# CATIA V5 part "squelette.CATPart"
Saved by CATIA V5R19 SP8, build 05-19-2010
Part number: squelette
Bounding box of the stored display mesh (mm): x -290.933 to 290.933, y 0 to 1220, z -52.5 to 105
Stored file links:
  G:\EU_thinkMotion\CFAO_2010\MMS_groupe2\MMS_groupe2\A reprendre\splanchenault\Planchenault\squelette.CATPart
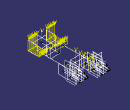
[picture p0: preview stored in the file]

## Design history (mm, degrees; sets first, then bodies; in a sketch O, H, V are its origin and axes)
Set1
  Plane1: type Offset, RefPlane zx-plane, Offset 200
  Plane2: type Offset, RefPlane zx-plane, Offset 300
  Plane3: type Offset, RefPlane yz-plane, Offset 200
  Plane4: type Offset, RefPlane yz-plane, Offset 200, reversed
  Plane5: type Offset, RefPlane zx-plane, Offset 750
  Plane6: type Offset, RefPlane zx-plane, Offset 850
  Plane7: type OffsetPt, RefPlane yz-plane, RefPoint Sketch6.P7
  Plane8: type OffsetPt, RefPlane Plane7, RefPoint Sketch6.P5
  Plane9: type OffsetPt, RefPlane Plane8, RefPoint Sketch7.P6
  Plane10: type OffsetPt, RefPlane Plane9, RefPoint Sketch7.P4
  Plane11: type OffsetPt, RefPlane Plane5, RefPoint Sketch8.P2
  Plane12: type OffsetPt, RefPlane Plane11, RefPoint Sketch13.P2
  Plane13: type OffsetPt, RefPlane Plane8, RefPoint Sketch14.P26
  Plane14: type OffsetPt, RefPlane Plane13, RefPoint Sketch14.P25
  Plane15: type OffsetPt, RefPlane Plane13, RefPoint Sketch14.P34
  Plane16: type OffsetPt, RefPlane Plane15, RefPoint Sketch14.P33
  Plane17: type OffsetPt, RefPlane Plane13, RefPoint Sketch14.P10
  Plane18: type OffsetPt, RefPlane Plane13, RefPoint Sketch14.P8
  Plane19: type OffsetPt, RefPlane Plane15, RefPoint Sketch15.P18
  Plane20: type OffsetPt, RefPlane Plane19, RefPoint Sketch15.P15
  Plane21: type OffsetPt, RefPlane Plane20, RefPoint Sketch15.P21
  Plane22: type OffsetPt, RefPlane Plane19, RefPoint Sketch15.P27
  Plane23: type OffsetPt, RefPlane Plane19, RefPoint Sketch15.P4
  Plane24: type OffsetPt, RefPlane Plane19, RefPoint Sketch15.P6
  Plane25: type OffsetPt, RefPlane Plane23, RefPoint Sketch15.P2
Body1 (main body)
  Sketch1 on yz-plane, origin (0, 0, 0), H (0, 1, 0), V (0, 0, 1)
    point P1 (0, 0)
    line L1 (0, 0) -> (380, 0)
    point P2 (380, 0)
    point P3 (380, 0)
    length L1 = 380
    coincidence: P1 O, P3 P2
    horizontal: L1 H
  Sketch2 on Plane1, origin (0, 200, 0), H (-1, 0, 0), V (0, 0, 1)
    point P1 (-200, 0)
    coincidence: P1 H
  Sketch3 on Plane2, origin (0, 300, 0), H (-1, 0, 0), V (0, 0, 1)
    point P1 (200, 0)
    coincidence: P1 H
  Sketch4 on Plane3, origin (200, 0, 0), H (0, 1, 0), V (0, 0, 1)
    line L1 (199.3543, 0) -> (749.3543, 0)
    point P1 (199.3543, 0)
    length L1 = 550
    coincidence: P1 H
    horizontal: L1 H
  Sketch5 on Plane4, origin (-200, 0, 0), H (0, 1, 0), V (0, 0, 1)
    line L1 (300, 0) -> (850, 0)
    point P1 (300, 0)
    length L1 = 550
    coincidence: P1 H
    horizontal: L1 H
  Sketch6 on Plane5, origin (0, 750, 0), H (-1, 0, 0), V (0, 0, 1)
    line L1 (-200, 0) -> (-200, 80)
    point P1 (-200, 0)
    point P2 (-200, 80)
    point P3 (-200, 80)
    point P4 (-200, 0)
    point P5 (-269.282, -40)
    line L2 (-200, 0) -> (-269.282, -40)
    point P7 (-130.718, -40)
    line L3 (-200, 0) -> (-130.718, -40)
    point P9 (-130.718, -40)
    point P10 (-269.282, -40)
    coincidence: P1 H, P3 P2, P4 P1, P9 P7, P10 P5
    vertical: L1 V
  Sketch7 on Plane6, origin (0, 850, 0), H (-1, 0, 0), V (0, 0, 1)
    line L1 (200, 0) -> (200, 80)
    point P1 (200, 0)
    point P2 (200, 80)
    point P3 (200, 80)
    point P4 (269.282, -40)
    line L2 (200, 0) -> (269.282, -40)
    point P6 (130.718, -40)
    line L3 (200, 0) -> (130.718, -40)
    coincidence: P1 H, P3 P2
    vertical: L1 V
  Sketch8 on Plane3, origin (200, 0, 0), H (0, 1, 0), V (0, 0, 1)
    line L1 (750, 80) -> (930, 80)
    point P2 (930, 80)
    point P3 (930, 80)
    length L1 = 180
    horizontal: L1 H
    coincidence: P3 P2
  Sketch9 on Plane8, origin (269.282, 0, 0), H (0, 1, 0), V (0, 0, 1)
    line L1 (750, -40) -> (930, -40)
    point P2 (930, -40)
    point P3 (930, -40)
    length L1 = 180
    horizontal: L1 H
    coincidence: P3 P2
  Sketch10 on Plane7, origin (130.718, 0, 0), H (0, 1, 0), V (0, 0, 1)
    line L1 (750, -40) -> (930, -40)
    point P2 (930, -40)
    point P3 (930, -40)
    length L1 = 180
    horizontal: L1 H
    coincidence: P3 P2
  Sketch11 on Plane9, origin (-130.718, 0, 0), H (0, 1, 0), V (0, 0, 1)
    line L1 (850, -40) -> (1030, -40)
    point P2 (1030, -40)
    point P3 (1030, -40)
    length L1 = 180
    horizontal: L1 H
    coincidence: P3 P2
  Sketch12 on Plane10, origin (-269.282, 0, 0), H (0, 1, 0), V (0, 0, 1)
    line L1 (850, -40) -> (1030, -40)
    point P2 (1030, -40)
    point P3 (1030, -40)
    length L1 = 180
    horizontal: L1 H
    coincidence: P3 P2
  Sketch13 on Plane4, origin (-200, 0, 0), H (0, 1, 0), V (0, 0, 1)
    line L1 (850, 80) -> (1030, 80)
    point P2 (1030, 80)
    point P3 (1030, 80)
    length L1 = 180
    horizontal: L1 H
    coincidence: P3 P2
  Sketch14 on Plane11, origin (0, 930, 0), H (-1, 0, 0), V (0, 0, 1)
    line L1 (-200, 80) -> (-200, 105)
    point P1 (-200, 80)
    point P2 (-200, 105)
    point P3 (-200, 105)
    construction line L2 (-235.7071, 100.6155) -> (-164.2929, 59.3845)
    construction line L3 (-235.7071, 59.3845) -> (-164.2929, 100.6155)
    point P8 (-178.3494, 67.5)
    point P9 (-200, 80)
    line L4 (-200, 80) -> (-178.3494, 67.5)
    point P10 (-221.6506, 67.5)
    point P11 (-200, 80)
    line L5 (-200, 80) -> (-221.6506, 67.5)
    point P12 (-178.3494, 67.5)
    point P13 (-221.6506, 67.5)
    construction line L6 (-130.718, -40) -> (-269.282, 40)
    point P14 (-269.282, 40)
    construction line L7 (-269.282, -40) -> (-130.718, 40)
    point P16 (-130.718, 40)
    point P18 (-247.6314, -52.5)
    point P19 (-269.282, -40)
    line L8 (-269.282, -40) -> (-247.6314, -52.5)
    point P20 (-269.282, -15)
    point P21 (-269.282, -40)
    line L9 (-269.282, -40) -> (-269.282, -15)
    point P22 (-290.9327, -52.5)
    point P23 (-269.282, -40)
    line L10 (-269.282, -40) -> (-290.9327, -52.5)
    point P24 (-269.282, -15)
    point P25 (-247.6314, -52.5)
    point P26 (-290.9327, -52.5)
    point P27 (-130.718, -15)
    point P28 (-130.718, -40)
    line L11 (-130.718, -40) -> (-130.718, -15)
    point P29 (-152.3686, -52.5)
    point P30 (-130.718, -40)
    line L12 (-130.718, -40) -> (-152.3686, -52.5)
    point P31 (-109.0673, -52.5)
    point P32 (-130.718, -40)
    line L13 (-130.718, -40) -> (-109.0673, -52.5)
    point P33 (-109.0673, -52.5)
    point P34 (-152.3686, -52.5)
    point P35 (-130.718, -15)
    length L1 = 25
    angle L3 L1 = 60
    angle L2 L1 = 60
    vertical: L1 V
    coincidence: P3 P2, L2 P1, L3 P1, P12 P8, P13 P10, P14 L5, P16 L4
    symmetry: P2 P8 L3, P1 P9 L3, L1 L4 L3, P2 P10 L4, P1 P11 L4, L1 L5 L4, P8 P18 L6, P9 P19 L6, L4 L8 L6, P10 P20 L6, P11 P21 L6, L5 L9 L6, P2 P22 L6, P1 P23 L6, L1 L10 L6, P13 P24 L6, P12 P25 L6, P3 P26 L6, P8 P27 L7, P9 P28 L7, L4 L11 L7, P10 P29 L7, P11 P30 L7, L5 L12 L7, P2 P31 L7, P1 P32 L7, L1 L13 L7, P3 P33 L7, P13 P34 L7, P12 P35 L7
    parallelism: L6 L4, L7 L3
  Sketch15 on Plane12, origin (0, 1030, 0), H (-1, 0, 0), V (0, 0, 1)
    line L1 (200, 80) -> (200, 105)
    point P2 (200, 105)
    point P3 (200, 105)
    point P4 (178.3494, 67.5)
    line L2 (200, 80) -> (178.3494, 67.5)
    point P6 (221.6506, 67.5)
    line L3 (200, 80) -> (221.6506, 67.5)
    point P8 (221.6506, 67.5)
    point P9 (178.3494, 67.5)
    line L4 (130.718, -40) -> (130.718, -15)
    point P12 (130.718, -15)
    line L5 (130.718, -40) -> (152.3686, -52.5)
    point P15 (152.3686, -52.5)
    line L6 (130.718, -40) -> (109.0673, -52.5)
    point P18 (109.0673, -52.5)
    line L7 (269.282, -40) -> (247.6314, -52.5)
    point P21 (247.6314, -52.5)
    line L8 (269.282, -40) -> (269.282, -15)
    point P24 (269.282, -15)
    line L9 (269.282, -40) -> (290.9327, -52.5)
    point P27 (290.9327, -52.5)
    length L1 = 25
    vertical: L1 V
    coincidence: P3 P2, P8 P6, P9 P4
  Sketch16 on Plane3, origin (200, 0, 0), H (0, 1, 0), V (0, 0, 1)
    line L1 (930, 105) -> (1120, 105)
    point P2 (1120, 105)
    reference projected line E1 (850, 80) -> (1030, 80) from Sketch13
    point P3 (1120, 105)
    distance L1 E1 = 25
    length L1 = 190
    horizontal: L1 H
    coincidence: P3 P2
  Sketch17 on Plane13, origin (290.9327, 0, 0), H (0, 1, 0), V (0, 0, 1)
    line L1 (930, -52.5) -> (1120, -52.5)
    point P2 (1120, -52.5)
    reference projected line E1 (850, -40) -> (1030, -40) from Sketch12
    point P3 (1120, -52.5)
    distance L1 E1 = 12.5
    length L1 = 190
    horizontal: L1 H
    coincidence: P3 P2
  Sketch18 on Plane17, origin (221.6506, 0, 0), H (0, 1, 0), V (0, 0, 1)
    line L1 (930, 67.5) -> (1120, 67.5)
    point P2 (1120, 67.5)
    reference projected line E1 (850, 80) -> (1030, 80) from Sketch13
    point P3 (1120, 67.5)
    distance L1 E1 = 12.5
    length L1 = 190
    horizontal: L1 H
    coincidence: P3 P2
  Sketch19 on Plane18, origin (178.3494, 0, 0), H (0, 1, 0), V (0, 0, 1)
    line L1 (930, 67.5) -> (1120, 67.5)
    point P2 (1120, 67.5)
    reference projected line E1 (850, 80) -> (1030, 80) from Sketch13
    point P3 (1120, 67.5)
    distance L1 E1 = 12.5
    length L1 = 190
    horizontal: L1 H
    coincidence: P3 P2
  Sketch20 on Plane7, origin (130.718, 0, 0), H (0, 1, 0), V (0, 0, 1)
    line L1 (930, -15) -> (1120, -15)
    point P2 (1120, -15)
    reference projected line E1 (850, -40) -> (1030, -40) from Sketch12
    point P3 (1120, -15)
    distance L1 E1 = 25
    length L1 = 190
    horizontal: L1 H
    coincidence: P3 P2
  Sketch21 on Plane16, origin (109.0673, 0, 0), H (0, 1, 0), V (0, 0, 1)
    line L1 (930, -52.5) -> (1120, -52.5)
    point P2 (1120, -52.5)
    reference projected line E1 (850, -40) -> (1030, -40) from Sketch12
    point P3 (1120, -52.5)
    distance L1 E1 = 12.5
    length L1 = 190
    horizontal: L1 H
    coincidence: P3 P2
  Sketch22 on Plane15, origin (152.3686, 0, 0), H (0, 1, 0), V (0, 0, 1)
    line L1 (930, -52.5) -> (1120, -52.5)
    point P2 (1120, -52.5)
    reference projected line E1 (850, -40) -> (1030, -40) from Sketch12
    point P3 (1120, -52.5)
    distance L1 E1 = 12.5
    length L1 = 190
    horizontal: L1 H
    coincidence: P3 P2
  Sketch23 on Plane14, origin (247.6314, 0, 0), H (0, 1, 0), V (0, 0, 1)
    line L1 (930, -52.5) -> (1120, -52.5)
    point P2 (1120, -52.5)
    reference projected line E1 (850, -40) -> (1030, -40) from Sketch12
    point P3 (1120, -52.5)
    distance L1 E1 = 12.5
    length L1 = 190
    horizontal: L1 H
    coincidence: P3 P2
  Sketch24 on Plane8, origin (269.282, 0, 0), H (0, 1, 0), V (0, 0, 1)
    line L1 (930, -15) -> (1120, -15)
    point P2 (1120, -15)
    reference projected line E1 (850, -40) -> (1030, -40) from Sketch12
    point P3 (1120, -15)
    distance L1 E1 = 25
    length L1 = 190
    horizontal: L1 H
    coincidence: P3 P2
  Sketch25 on Plane25, origin (-200, 0, 0), H (0, 1, 0), V (0, 0, 1)
    line L1 (1030, 105) -> (1220, 105)
    point P2 (1220, 105)
    reference projected line E1 (850, 80) -> (1030, 80) from Sketch13
    point P3 (1220, 105)
    distance L1 E1 = 25
    length L1 = 190
    horizontal: L1 H
    coincidence: P3 P2
  Sketch26 on Plane24, origin (-221.6506, 0, 0), H (0, 1, 0), V (0, 0, 1)
    line L1 (1030, 67.5) -> (1220, 67.5)
    point P2 (1220, 67.5)
    reference projected line E1 (850, 80) -> (1030, 80) from Sketch13
    point P3 (1220, 67.5)
    distance L1 E1 = 12.5
    horizontal: L1 H
    coincidence: P3 P2
  Sketch27 on Plane23, origin (-178.3494, 0, 0), H (0, 1, 0), V (0, 0, 1)
    line L1 (1030, 67.5) -> (1220, 67.5)
    point P2 (1220, 67.5)
    reference projected line E1 (850, 80) -> (1030, 80) from Sketch13
    point P3 (1220, 67.5)
    distance L1 E1 = 12.5
    horizontal: L1 H
    coincidence: P3 P2
  Sketch28 on Plane10, origin (-269.282, 0, 0), H (0, 1, 0), V (0, 0, 1)
    line L1 (1030, -15) -> (1220, -15)
    point P2 (1220, -15)
    reference projected line E1 (850, -40) -> (1030, -40) from Sketch12
    point P3 (1220, -15)
    distance L1 E1 = 25
    horizontal: L1 H
    coincidence: P3 P2
  Sketch29 on Plane22, origin (-290.9327, 0, 0), H (0, 1, 0), V (0, 0, 1)
    line L1 (1030, -52.5) -> (1220, -52.5)
    point P2 (1220, -52.5)
    reference projected line E1 (850, -40) -> (1030, -40) from Sketch12
    point P3 (1220, -52.5)
    distance L1 E1 = 12.5
    horizontal: L1 H
    coincidence: P3 P2
  Sketch30 on Plane21, origin (-247.6314, 0, 0), H (0, 1, 0), V (0, 0, 1)
    line L1 (1030, -52.5) -> (1220, -52.5)
    point P2 (1220, -52.5)
    reference projected line E1 (850, -40) -> (1030, -40) from Sketch12
    point P3 (1220, -52.5)
    distance L1 E1 = 12.5
    horizontal: L1 H
    coincidence: P3 P2
  Sketch31 on Plane9, origin (-130.718, 0, 0), H (0, 1, 0), V (0, 0, 1)
    line L1 (1030, -15) -> (1220, -15)
    point P2 (1220, -15)
    reference projected line E1 (850, -40) -> (1030, -40) from Sketch12
    point P3 (1220, -15)
    distance L1 E1 = 25
    horizontal: L1 H
    coincidence: P3 P2
  Sketch32 on Plane20, origin (-152.3686, 0, 0), H (0, 1, 0), V (0, 0, 1)
    line L1 (1030, -52.5) -> (1220, -52.5)
    point P2 (1220, -52.5)
    reference projected line E1 (850, -40) -> (1030, -40) from Sketch12
    point P3 (1220, -52.5)
    distance E1 L1 = 12.5
    horizontal: L1 H
    coincidence: P3 P2
  Sketch33 on Plane19, origin (-109.0673, 0, 0), H (0, 1, 0), V (0, 0, 1)
    line L1 (1030, -52.5) -> (1220, -52.5)
    point P2 (1220, -52.5)
    reference projected line E1 (850, -40) -> (1030, -40) from Sketch12
    point P3 (1220, -52.5)
    distance L1 E1 = 12.5
    horizontal: L1 H
    coincidence: P3 P2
